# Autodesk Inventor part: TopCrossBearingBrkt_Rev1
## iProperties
Created: 2008-11
Part Number: TopCrossBearingBrkt_Rev1
Document SubType Name: Modeling
Designer: ETUDIANT
Author: ETUDIANT
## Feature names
1. Base1
2. Extrusion1
3. Extrusion2
